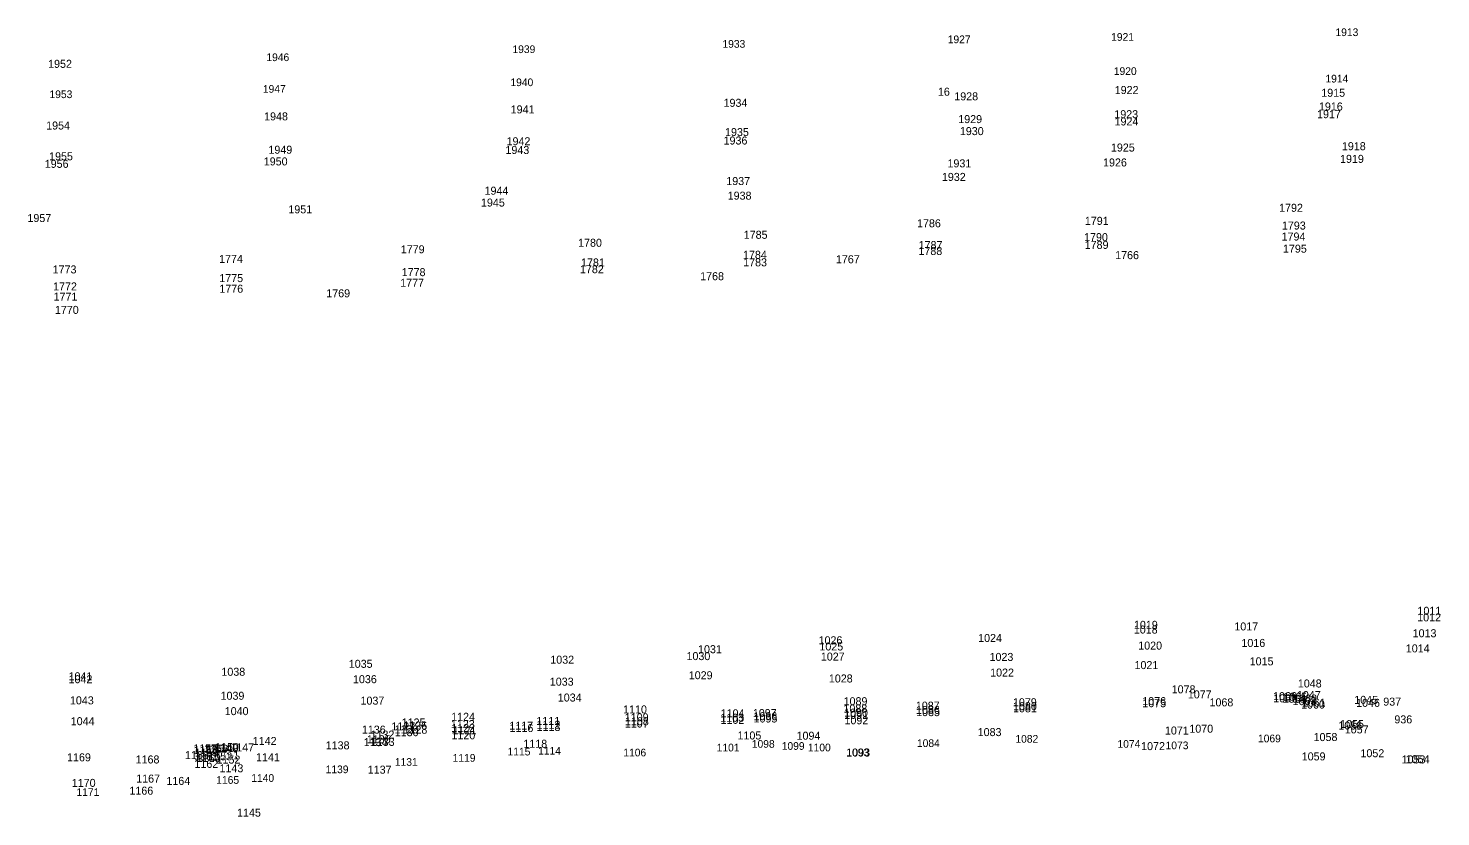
# Model space of a CAD drawing. Extents: x 359002 to 361405, y 1522603 to 1525369.
# Drawn here: x 359001.8 to 359443.1, y 1524604 to 1524850.4 of the extents above; entities that cross this region are included whole.
import ezdxf

# ---------------------------------------------------------------- set-up
doc = ezdxf.new("R2010")
doc.units = 0
for name, color, linetype in [('CBS_I', 7, 'Continuous'), ('DHW_I', 7, 'Continuous'), ('DINV_I', 7, 'Continuous'), ('DS_I', 7, 'Continuous'), ('LABL_I', 7, 'Continuous'), ('LELB_I', 7, 'Continuous'), ('LELS_I', 7, 'Continuous'), ('LFNC_I', 7, 'Continuous'), ('LUKP_I', 7, 'Continuous'), ('RC_I', 7, 'Continuous'), ('RDP_I', 7, 'Continuous'), ('RDU_I', 7, 'Continuous'), ('RGW_I', 7, 'Continuous'), ('S_I', 7, 'Continuous'), ('SDEL_I', 7, 'Continuous'), ('SRM_I', 7, 'Continuous'), ('UG_I', 7, 'Continuous'), ('ULP_I', 7, 'Continuous'), ('USMH_I', 7, 'Continuous'), ('UUMH_I', 7, 'Continuous'), ('UWV_I', 7, 'Continuous')]:
    doc.layers.add(name, color=color, linetype=linetype)

msp = doc.modelspace()

# ---------------------------------------------------------------- texts
at = {"layer": 'CBS_I'}
for s, p in [('16', (359286.03, 1524829.28)), ('1145', (359067.06, 1524604.08))]:
    msp.add_text(s, height=2.501, dxfattribs=at).set_placement(p)
at = {"layer": 'DHW_I'}
for s, p in [('1157', (359053.38, 1524624.15)), ('1150', (359060.21, 1524624.59))]:
    msp.add_text(s, height=2.501, dxfattribs=at).set_placement(p)
at = {"layer": 'DINV_I'}
for s, p in [('1161', (359053.68, 1524621.68)), ('1156', (359056.75, 1524624.05))]:
    msp.add_text(s, height=2.501, dxfattribs=at).set_placement(p)
at = {"layer": 'DS_I'}
for s, p in [('1092', (359256.84, 1524632.93)), ('1135', (359107.61, 1524627)), ('1120', (359134.05, 1524628.24)), ('1118', (359156.51, 1524625.59)), ('1105', (359223.42, 1524628.19)), ('1072', (359349.52, 1524624.86))]:
    msp.add_text(s, height=2.501, dxfattribs=at).set_placement(p)
at = {"layer": 'LABL_I'}
for s, p in [('1935', (359219.53, 1524816.68)), ('1955', (359008.34, 1524809.11)), ('1791', (359331.94, 1524788.95)), ('1792', (359392.63, 1524793.03)), ('1785', (359225.36, 1524784.6)), ('1786', (359279.51, 1524788.18)), ('1779', (359118.22, 1524780.06)), ('1780', (359173.62, 1524782.1)), ('1774', (359061.45, 1524777.06)), ('1773', (359009.45, 1524773.77)), ('1014', (359432.21, 1524655.39)), ('1022', (359302.35, 1524647.84)), ('1021', (359347.45, 1524650.17)), ('1015', (359383.44, 1524651.34)), ('1028', (359251.96, 1524645.99)), ('1048', (359398.49, 1524644.43)), ('1037', (359105.63, 1524639.07)), ('1034', (359167.27, 1524640.04)), ('1089', (359256.57, 1524638.88)), ('1078', (359359.07, 1524642.6)), ('1045', (359416.11, 1524639.31)), ('1040', (359063.21, 1524635.79)), ('1110', (359187.68, 1524636.33)), ('1044', (359015.09, 1524632.65)), ('1136', (359106.06, 1524630.01)), ('1125', (359118.49, 1524632.25)), ('1124', (359133.95, 1524634.02)), ('936', (359428.64, 1524633.21)), ('1141', (359072.99, 1524621.39)), ('1170', (359015.43, 1524613.37)), ('1167', (359035.55, 1524614.71))]:
    msp.add_text(s, height=2.501, dxfattribs=at).set_placement(p)
at = {"layer": 'LELB_I'}
for s, p in [('1922', (359341.27, 1524829.81)), ('1915', (359405.81, 1524828.96)), ('1934', (359219.06, 1524825.82)), ('1928', (359291.15, 1524827.84)), ('1916', (359405.08, 1524824.67)), ('1948', (359075.52, 1524821.58)), ('1941', (359152.55, 1524823.76)), ('1929', (359292.39, 1524820.73)), ('1923', (359341.15, 1524822.26)), ('1924', (359341.22, 1524820)), ('1917', (359404.49, 1524822.27)), ('1954', (359007.42, 1524818.73)), ('1935', (359219.53, 1524816.68)), ('1930', (359292.89, 1524816.98)), ('1949', (359076.86, 1524811.16)), ('1943', (359150.92, 1524811.08)), ('1942', (359151.27, 1524813.81)), ('1936', (359219.07, 1524814.04)), ('1925', (359340.09, 1524811.85)), ('1918', (359412.25, 1524812.27)), ('1956', (359006.98, 1524806.76)), ('1955', (359008.34, 1524809.11)), ('1950', (359075.41, 1524807.51)), ('1931', (359289.02, 1524806.9)), ('1926', (359337.63, 1524807.19)), ('1919', (359411.67, 1524808.31)), ('1932', (359287.28, 1524802.67)), ('1944', (359144.39, 1524798.36)), ('1937', (359219.91, 1524801.38)), ('1945', (359143.27, 1524794.66)), ('1938', (359220.35, 1524796.82)), ('1957', (359001.57, 1524789.83)), ('1951', (359083.09, 1524792.54)), ('1951', (359083.09, 1524792.54)), ('1793', (359393.51, 1524787.48)), ('1787', (359280.01, 1524781.38)), ('1790', (359331.7, 1524783.86)), ('1789', (359331.89, 1524781.43)), ('1794', (359393.41, 1524784.05)), ('1781', (359174.54, 1524775.94)), ('1784', (359225.14, 1524778.34)), ('1783', (359225.19, 1524775.98)), ('1788', (359279.95, 1524779.52)), ('1778', (359118.5, 1524772.92)), ('1782', (359174.2, 1524773.85)), ('1772', (359009.59, 1524768.46)), ('1775', (359061.51, 1524771.06)), ('1776', (359061.53, 1524767.75)), ('1777', (359118.03, 1524769.59)), ('1771', (359009.74, 1524765.27)), ('1018', (359347.24, 1524661.27)), ('1017', (359378.65, 1524662.25)), ('1012', (359435.77, 1524665.08)), ('1024', (359298.6, 1524658.64)), ('1016', (359380.86, 1524657.09)), ('1013', (359434.35, 1524660.12)), ('1030', (359207.48, 1524652.98)), ('1025', (359249, 1524655.99)), ('1027', (359249.46, 1524652.83)), ('1023', (359302.16, 1524652.72)), ('1020', (359348.62, 1524656.26)), ('1038', (359062.17, 1524648.09)), ('1035', (359101.97, 1524650.57)), ('1032', (359164.93, 1524651.86)), ('1042', (359014.42, 1524645.76)), ('1036', (359103.28, 1524645.77)), ('1033', (359164.77, 1524644.99)), ('1029', (359208.19, 1524647)), ('1043', (359014.85, 1524639.15)), ('1039', (359061.91, 1524640.59)), ('1077', (359364.11, 1524641.02)), ('1047', (359398.19, 1524640.8)), ('1045', (359416.11, 1524639.31)), ('937', (359425.17, 1524638.76)), ('1104', (359218.15, 1524635.11)), ('1097', (359228.2, 1524635.18)), ('1088', (359256.52, 1524636.61)), ('1087', (359279.14, 1524637.51)), ('1079', (359309.47, 1524638.56)), ('1136', (359106.06, 1524630.01)), ('1127', (359115.26, 1524631.02)), ('1126', (359118.99, 1524631.31)), ('1123', (359133.86, 1524631.73)), ('1111', (359160.57, 1524632.71)), ('1109', (359188.2, 1524633.85)), ('1142', (359071.96, 1524626.47)), ('1169', (359013.95, 1524621.36)), ('1163', (359050.79, 1524622.05)), ('1163', (359050.79, 1524622.05)), ('1163', (359050.79, 1524622.05)), ('1157', (359053.38, 1524624.15)), ('1158', (359053.54, 1524623.61)), ('1159', (359053.84, 1524622.84)), ('1160', (359054.4, 1524621.14)), ('1160', (359054.4, 1524621.14)), ('1155', (359055.93, 1524623.94)), ('1155', (359055.93, 1524623.94)), ('1154', (359057.57, 1524624.07)), ('1153', (359058.1, 1524621.68)), ('1149', (359060, 1524624.27)), ('1150', (359060.21, 1524624.59)), ('1151', (359060.35, 1524622.03)), ('1148', (359062.89, 1524621.95)), ('1148', (359062.89, 1524621.95)), ('1147', (359064.95, 1524624.46)), ('1147', (359064.95, 1524624.46)), ('1147', (359064.95, 1524624.46)), ('1168', (359035.37, 1524620.69)), ('1162', (359053.75, 1524619.32)), ('1152', (359060.66, 1524620.65))]:
    msp.add_text(s, height=2.501, dxfattribs=at).set_placement(p)
at = {"layer": 'LELS_I'}
for s, p in [('1921', (359340.15, 1524846.44)), ('1913', (359410.25, 1524847.92)), ('1939', (359153.11, 1524842.61)), ('1933', (359218.71, 1524844.27)), ('1927', (359289.1, 1524845.7)), ('1946', (359076.22, 1524840.1)), ('1920', (359340.99, 1524835.77)), ('1914', (359407.11, 1524833.42)), ('1947', (359075.13, 1524830.21)), ('1940', (359152.47, 1524832.28)), ('1953', (359008.46, 1524828.54)), ('1098', (359227.89, 1524625.6)), ('1084', (359279.48, 1524625.84)), ('1082', (359310.24, 1524627.18)), ('1074', (359342.13, 1524625.6)), ('1069', (359386.03, 1524627.3)), ('1119', (359134.41, 1524621.23)), ('1115', (359151.57, 1524623.2)), ('1114', (359161.12, 1524623.46)), ('1106', (359187.74, 1524622.9)), ('1101', (359216.91, 1524624.45)), ('1099', (359237.24, 1524624.95)), ('1100', (359245.41, 1524624.48)), ('1093', (359257.4, 1524622.95)), ('1073', (359357.16, 1524625.14)), ('1139', (359094.74, 1524617.66)), ('1131', (359116.36, 1524619.97)), ('1165', (359060.56, 1524614.34)), ('1140', (359071.51, 1524614.95)), ('1171', (359016.9, 1524610.54))]:
    msp.add_text(s, height=2.4, dxfattribs=at).set_placement(p)
at = {"layer": 'LFNC_I'}
msp.add_text('1952', height=2.501, dxfattribs=at).set_placement((359008.03, 1524838))
at = {"layer": 'LUKP_I'}
for s, p in [('1083', (359298.46, 1524629.24)), ('1093', (359257.4, 1524622.85)), ('1137', (359107.89, 1524617.51))]:
    msp.add_text(s, height=2.501, dxfattribs=at).set_placement(p)
at = {"layer": 'RC_I'}
for s, p in [('1076', (359349.88, 1524638.92)), ('1066', (359390.74, 1524640.47)), ('1065', (359393.92, 1524640.27)), ('1062', (359397.05, 1524639.71)), ('1090', (359256.73, 1524635.3)), ('1086', (359279.19, 1524636.15)), ('1080', (359309.5, 1524637.33)), ('1061', (359399.73, 1524638.43)), ('1129', (359116.28, 1524630.09)), ('1128', (359119.07, 1524629.99)), ('1122', (359133.97, 1524630.51)), ('1117', (359152.13, 1524631.24)), ('1112', (359160.63, 1524631.55)), ('1108', (359188.26, 1524632.63)), ('1103', (359218.04, 1524633.73)), ('1096', (359228.4, 1524634.2)), ('1055', (359411.7, 1524631.77)), ('1130', (359116.33, 1524629.21)), ('1054', (359432.21, 1524620.78))]:
    msp.add_text(s, height=2.501, dxfattribs=at).set_placement(p)
at = {"layer": 'RDP_I'}
for s, p in [('1067', (359390.79, 1524639.78)), ('1064', (359393.74, 1524639.65)), ('1063', (359396.86, 1524638.91)), ('1091', (359256.78, 1524634.62)), ('1085', (359279.23, 1524635.48)), ('1081', (359309.5, 1524636.67)), ('1075', (359349.9, 1524638.26)), ('1060', (359399.5, 1524637.83)), ('1116', (359152.19, 1524630.51)), ('1113', (359160.65, 1524630.84)), ('1107', (359188.21, 1524631.91)), ('1102', (359218.12, 1524633.07)), ('1095', (359228.44, 1524633.49)), ('1056', (359411.15, 1524631.3)), ('1134', (359106.64, 1524626.1)), ('1132', (359108.78, 1524628.46)), ('1133', (359108.84, 1524626.19)), ('1130', (359116.33, 1524629.21)), ('1121', (359134.39, 1524629.8)), ('1141', (359072.99, 1524621.39)), ('1138', (359094.76, 1524625.1)), ('1143', (359061.58, 1524617.94)), ('1053', (359430.91, 1524620.7)), ('1164', (359044.99, 1524613.99)), ('1166', (359033.43, 1524610.94))]:
    msp.add_text(s, height=2.501, dxfattribs=at).set_placement(p)
at = {"layer": 'RDU_I'}
for s, p in [('1170', (359015.43, 1524613.37)), ('1167', (359035.55, 1524614.71)), ('1164', (359044.99, 1524613.99))]:
    msp.add_text(s, height=2.501, dxfattribs=at).set_placement(p)
at = {"layer": 'RGW_I'}
for s, p in [('1795', (359393.84, 1524780.26)), ('1770', (359010.15, 1524761.13)), ('1011', (359435.86, 1524667.14)), ('1019', (359347.28, 1524662.75)), ('1026', (359248.75, 1524657.92)), ('1041', (359014.41, 1524646.68))]:
    msp.add_text(s, height=2.501, dxfattribs=at).set_placement(p)
at = {"layer": 'S_I'}
for s, p in [('1767', (359254.16, 1524776.94)), ('1077', (359364.11, 1524641.02))]:
    msp.add_text(s, height=2.501, dxfattribs=at).set_placement(p)
at = {"layer": 'SDEL_I'}
for s, p in [('1766', (359341.41, 1524778.23)), ('1768', (359211.75, 1524771.65)), ('1018', (359347.24, 1524661.27)), ('1031', (359211.09, 1524655.14))]:
    msp.add_text(s, height=2.501, dxfattribs=at).set_placement(p)
at = {"layer": 'SRM_I'}
for s, p in [('1769', (359094.94, 1524766.31)), ('1035', (359101.97, 1524650.57))]:
    msp.add_text(s, height=2.501, dxfattribs=at).set_placement(p)
at = {"layer": 'UG_I'}
for s, p in [('1057', (359413.15, 1524630.08)), ('1058', (359403.41, 1524627.69)), ('1059', (359399.7, 1524621.65))]:
    msp.add_text(s, height=2.501, dxfattribs=at).set_placement(p)
at = {"layer": 'ULP_I'}
msp.add_text('1046', height=2.501, dxfattribs=at).set_placement((359416.7, 1524638.38))
at = {"layer": 'USMH_I'}
msp.add_text('1094', height=2.501, dxfattribs=at).set_placement((359241.87, 1524628.11))
at = {"layer": 'UUMH_I'}
for s, p in [('1070', (359364.59, 1524630.3)), ('1071', (359356.96, 1524629.73))]:
    msp.add_text(s, height=2.501, dxfattribs=at).set_placement(p)
at = {"layer": 'UWV_I'}
for s, p in [('1068', (359370.89, 1524638.53)), ('1052', (359418.05, 1524622.64))]:
    msp.add_text(s, height=2.501, dxfattribs=at).set_placement(p)

doc.saveas('drawing.dxf')
